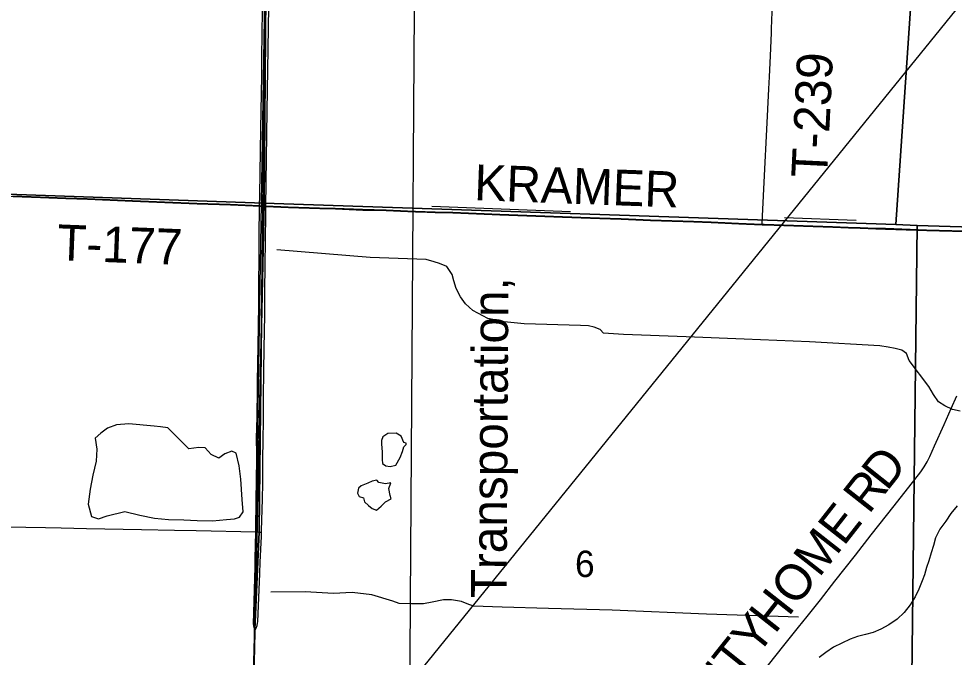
# Model space of a CAD drawing. Extents: x -107 to 120, y -81 to 213.
# Drawn here: x -76.39 to -68.55, y -24.78 to -19.43 of the extents above; entities that cross this region are included whole.
import ezdxf

# ---------------------------------------------------------------- set-up
doc = ezdxf.new("R2010")
doc.units = 0
for name, color, linetype in [('Default', 7, 'Continuous'), ('GM_X_Major_River', 7, 'Continuous'), ('GM_X_Minor_Lake', 7, 'Continuous'), ('GM_X_Minor_River', 7, 'Continuous'), ('GM_X_Rail_Line', 7, 'Continuous'), ('GM_X_Rail_Line_Text', 7, 'Continuous'), ('GM_X_Section', 7, 'Continuous'), ('GM_X_Section_Text', 7, 'Continuous'), ('GM_X_State_Route', 7, 'Continuous'), ('GM_X_Township', 7, 'Continuous'), ('GM_X_Township_Road', 7, 'Continuous'), ('GM_X_Township_Road_Text', 7, 'Continuous')]:
    doc.layers.add(name, color=color, linetype=linetype)

msp = doc.modelspace()

# ---------------------------------------------------------------- linework, layer by layer
at = {"layer": 'Default'}
msp.add_line((-74.4427, -26.637), (119.9981, 213.2739), dxfattribs=at)
at = {"layer": 'GM_X_Major_River'}
msp.add_lwpolyline([(-68.5289, -23.5056), (-68.5812, -23.5716), (-68.6254, -23.6357), (-68.6737, -23.7037), (-68.712, -23.7738), (-68.7262, -23.838), (-68.7464, -23.9001), (-68.7667, -23.9682), (-68.7849, -24.0223), (-68.8031, -24.0844), (-68.8213, -24.1345), (-68.8495, -24.2047), (-68.8818, -24.2687), (-68.9221, -24.3368), (-68.9723, -24.3989), (-69.0326, -24.4548), (-69.1009, -24.5028), (-69.1691, -24.5407), (-69.2333, -24.5666), (-69.2975, -24.5844), (-69.3636, -24.6023), (-69.4258, -24.6242), (-69.494, -24.6561), (-69.5662, -24.69), (-69.6305, -24.7339), (-69.6847, -24.7759)], dxfattribs=at)
at = {"layer": 'GM_X_Minor_Lake'}
for p, q in [((-75.2541, -22.84), (-75.4664, -22.8213)), ((-73.3514, -22.99), (-73.3456, -23.0542)), ((-73.4646, -23.3166), (-73.5208, -23.3405))]:
    msp.add_line(p, q, dxfattribs=at)
for points in [[(-75.4664, -22.8213), (-75.5706, -22.829), (-75.6449, -22.8569), (-75.7031, -22.8989), (-75.7493, -22.9408), (-75.7355, -23.0311), (-75.7419, -23.1334), (-75.7683, -23.2497), (-75.7907, -23.3679), (-75.8091, -23.4943), (-75.7793, -23.5966), (-75.7213, -23.6169), (-75.6491, -23.591), (-75.5007, -23.5553), (-75.3746, -23.5858), (-75.2525, -23.6102), (-75.1343, -23.6226), (-75.0061, -23.625), (-74.8939, -23.6293), (-74.7657, -23.6317), (-74.6495, -23.622), (-74.5814, -23.6162), (-74.5413, -23.6023), (-74.5111, -23.5583), (-74.5188, -23.4539), (-74.5303, -23.2834), (-74.544, -23.171), (-74.5677, -23.0647), (-74.6057, -23.0485), (-74.6619, -23.0724), (-74.714, -23.1084), (-74.7781, -23.0781), (-74.828, -23.0218), (-74.8801, -23.0176), (-74.9662, -23.0294), (-75.0242, -22.9711), (-75.098, -22.8946), (-75.14, -22.8544), (-75.2021, -22.8442), (-75.2541, -22.84)], [(-73.3456, -23.0542), (-73.3457, -23.0823), (-73.3458, -23.1184), (-73.3439, -23.1525), (-73.3159, -23.1726), (-73.2778, -23.1768), (-73.2317, -23.1669), (-73.1955, -23.1028), (-73.1753, -23.0527), (-73.1632, -23.0126), (-73.1451, -22.9926), (-73.145, -22.9826), (-73.165, -22.9765), (-73.1869, -22.9223), (-73.2289, -22.8981), (-73.299, -22.9019), (-73.3412, -22.9299), (-73.3513, -22.9599), (-73.3514, -22.99)], [(-73.5208, -23.3405), (-73.5448, -23.3585), (-73.553, -23.4006), (-73.537, -23.4287), (-73.503, -23.4409), (-73.4931, -23.473), (-73.4591, -23.5052), (-73.4292, -23.5293), (-73.3931, -23.5435), (-73.355, -23.5095), (-73.3188, -23.4735), (-73.2707, -23.4496), (-73.2786, -23.4195), (-73.2884, -23.3613), (-73.2723, -23.3152), (-73.3184, -23.3231), (-73.3744, -23.3129), (-73.3904, -23.2928), (-73.4285, -23.3007), (-73.4646, -23.3166)]]:
    msp.add_lwpolyline(points, dxfattribs=at)
at = {"layer": 'GM_X_Minor_River'}
for points in [[(-71.7668, -21.0449), (-72.9286, -20.9994)], [(-69.375, -21.1161), (-69.976, -21.0943)], [(-68.5044, -22.7153), (-68.5685, -22.7011), (-68.6325, -22.6688), (-68.6845, -22.6346), (-68.7284, -22.5743), (-68.7662, -22.508), (-68.9318, -22.2888), (-68.9537, -22.2306), (-68.9917, -22.2024), (-69.0497, -22.1882), (-69.1078, -22.178), (-69.1759, -22.1658), (-69.7668, -22.134), (-70.3136, -22.1123), (-70.8004, -22.0928), (-71.3252, -22.0732), (-71.4914, -22.0607), (-71.5194, -22.0306), (-71.5694, -22.0103), (-71.6175, -22.0002), (-71.6836, -21.998), (-72.1563, -21.9826), (-72.3241, -21.9654), (-72.4607, -21.9375), (-72.5867, -21.871), (-72.6466, -21.8146), (-72.6885, -21.7563), (-72.7244, -21.686), (-72.7462, -21.6238), (-72.7601, -21.5696), (-72.804, -21.5013), (-72.864, -21.477), (-72.91, -21.4628), (-72.9761, -21.4446), (-73.4468, -21.4272), (-74.2279, -21.3627)], [(-69.8579, -24.4384), (-70.6292, -24.4141), (-71.4184, -24.3797), (-71.9532, -24.3661), (-72.3399, -24.3549), (-72.5802, -24.3462), (-72.6323, -24.328), (-72.6823, -24.3078), (-72.7644, -24.2935), (-72.8325, -24.2953), (-72.9267, -24.3131), (-72.9989, -24.3269), (-73.101, -24.3266), (-73.2032, -24.3263), (-73.2572, -24.3041), (-73.4314, -24.2534), (-73.5956, -24.2329), (-73.7539, -24.2404), (-73.9902, -24.2277), (-74.2767, -24.2289)]]:
    msp.add_lwpolyline(points, dxfattribs=at)
at = {"layer": 'GM_X_Rail_Line'}
for points in [[(-73.2734, -42.3003), (-73.2649, -39.1049), (-73.2216, -37.066), (-73.1836, -32.1627), (-73.1217, -26.6694), (-73.1077, -24.2984), (-73.0594, -17.2912), (-73.0254, -15.4202), (-73.0009, -14.7079), (-72.9769, -14.4026), (-72.9056, -13.7921), (-72.6989, -11.6944), (-72.6592, -11.2717), (-72.6185, -10.8402), (-72.6072, -10.5527), (-72.6015, -10.2681), (-72.5873, -9.1338), (-72.5717, -7.0133)], [(-74.7234, -53.134), (-74.6362, -47.8623), (-74.5798, -37.2388), (-74.4951, -29.4853), (-74.4481, -26.6247), (-74.401, -23.7172), (-74.3109, -18.2221), (-74.335, -14.312), (-74.2191, -9.0155)]]:
    msp.add_lwpolyline(points, dxfattribs=at)
at = {"layer": 'GM_X_Section'}
for points in [[(-79.7136, -15.4834), (-74.2995, -15.6503), (-74.2925, -15.7245), (-74.3332, -20.9721), (-79.6709, -20.7861)], [(-74.2925, -15.7245), (-68.6864, -15.892), (-69.0434, -21.1516), (-74.3332, -20.9721)], [(-68.6864, -15.892), (-63.3999, -15.981), (-63.5863, -21.3171), (-68.8654, -21.1579), (-69.0434, -21.1516)], [(-79.6709, -20.7861), (-74.3332, -20.9721), (-74.4572, -26.6128), (-79.8137, -26.4946)], [(-74.3332, -20.9721), (-69.0434, -21.1516), (-68.8654, -21.1579), (-68.9331, -27.0735), (-74.4587, -26.8789), (-74.4572, -26.6128)], [(-68.8654, -21.1579), (-63.5863, -21.3171), (-63.5383, -21.3196), (-63.6604, -27.1446), (-68.9331, -27.0735)]]:
    msp.add_lwpolyline(points, close=True, dxfattribs=at)
at = {"layer": 'GM_X_State_Route'}
msp.add_line((-74.4046, -23.726), (-74.4002, -23.4428), dxfattribs=at)
for points in [[(-74.3725, -20.9978), (-74.3714, -20.9063), (-74.362, -20.3485), (-74.3545, -19.9055), (-74.3542, -19.7578), (-74.3534, -19.7087), (-74.3498, -19.5948), (-74.3468, -19.3159), (-74.3464, -19.2339), (-74.3403, -18.9551), (-74.3391, -18.8566), (-74.339, -18.8445)], [(-74.3189, -21.0001), (-74.3078, -20.1988), (-74.3036, -19.8543), (-74.296, -19.3292), (-74.2938, -19.1324), (-74.2919, -19.001), (-74.2894, -18.8863), (-74.2892, -18.8451)], [(-74.4002, -23.4428), (-74.3998, -23.4165), (-74.3994, -23.3345), (-74.3955, -23.072), (-74.3968, -22.9407), (-74.3927, -22.7604), (-74.3902, -22.5306), (-74.3889, -22.4651), (-74.3837, -22.1698), (-74.3798, -21.8252), (-74.3755, -21.2509), (-74.3725, -20.9978)], [(-74.3489, -23.4502), (-74.3462, -23.3161), (-74.3457, -23.1027), (-74.343, -22.9715), (-74.3401, -22.7747), (-74.3385, -22.6106), (-74.3355, -22.3645), (-74.3305, -22.0363), (-74.3282, -21.9216), (-74.3273, -21.7083), (-74.3198, -21.0684), (-74.3189, -21.0001)], [(-74.3575, -23.7646), (-74.3558, -23.7271), (-74.3553, -23.7139), (-74.3489, -23.4502)], [(-74.4084, -23.9804), (-74.4081, -23.9517), (-74.4046, -23.726)], [(-74.4098, -24.5459), (-74.4008, -24.532), (-74.3926, -24.5098), (-74.3894, -24.491), (-74.3878, -24.4771), (-74.3701, -24.0732), (-74.3671, -23.9787), (-74.3575, -23.7646)], [(-74.4098, -24.5459), (-74.418, -24.527), (-74.4213, -24.5123), (-74.4227, -24.4926), (-74.4193, -24.4018), (-74.4094, -24.0181), (-74.4084, -23.9804)], [(-74.4313, -25.7287), (-74.4303, -25.5642), (-74.4297, -25.5388), (-74.4285, -25.4823), (-74.4272, -25.3597), (-74.4264, -25.2802), (-74.4258, -25.2195), (-74.4244, -25.0885), (-74.4234, -25.0056), (-74.4223, -24.9089), (-74.4212, -24.8458), (-74.4201, -24.8081), (-74.4098, -24.5459)]]:
    msp.add_lwpolyline(points, dxfattribs=at)
at = {"layer": 'GM_X_Township'}
for points in [[(-74.3142, -18.8422), (-74.3456, -20.996), (-74.3737, -20.9948), (-74.618, -20.9846), (-74.8969, -20.9752), (-75.4379, -20.9519), (-75.8151, -20.9365), (-75.9954, -20.9291), (-76.2087, -20.9219), (-76.4383, -20.9136)], [(-68.3586, -21.2105), (-68.7852, -21.1985), (-69.1297, -21.1857), (-69.2117, -21.1831), (-69.3429, -21.1789), (-69.4412, -21.1749), (-69.5724, -21.1691), (-69.8185, -21.1608), (-70.1467, -21.1507), (-70.1648, -21.1499), (-70.3598, -21.1411), (-70.5896, -21.1323), (-70.7371, -21.1265), (-71.098, -21.114), (-71.344, -21.1029), (-71.5245, -21.0969), (-71.8362, -21.0868), (-71.9838, -21.081), (-72.3611, -21.0681), (-72.7548, -21.0515), (-72.9025, -21.047), (-73.0664, -21.0413), (-73.1319, -21.0388), (-73.3122, -21.0316), (-73.5091, -21.0266), (-73.7387, -21.0179), (-73.87, -21.013), (-74.1325, -21.0056), (-74.3201, -20.9972), (-74.3456, -20.996), (-74.3142, -18.8422)], [(-76.4383, -20.9136), (-76.2087, -20.9219), (-75.9954, -20.9291), (-75.8151, -20.9365), (-75.4379, -20.9519), (-74.8969, -20.9752), (-74.618, -20.9846), (-74.3737, -20.9948), (-74.3456, -20.996), (-74.3736, -23.4486), (-74.3768, -23.7238), (-74.411, -24.543), (-74.4213, -24.8052)], [(-74.4213, -24.8052), (-74.411, -24.543), (-74.3768, -23.7238), (-74.3736, -23.4486), (-74.3456, -20.996), (-74.3201, -20.9972), (-74.1325, -21.0056), (-73.87, -21.013), (-73.7387, -21.0179), (-73.5091, -21.0266), (-73.3122, -21.0316), (-73.1319, -21.0388), (-73.0664, -21.0413), (-72.9025, -21.047), (-72.7548, -21.0515), (-72.3611, -21.0681), (-71.9838, -21.081), (-71.8362, -21.0868), (-71.5245, -21.0969), (-71.344, -21.1029), (-71.098, -21.114), (-70.7371, -21.1265), (-70.5896, -21.1323), (-70.3598, -21.1411), (-70.1648, -21.1499), (-70.1467, -21.1507), (-69.8185, -21.1608), (-69.5724, -21.1691), (-69.4412, -21.1749), (-69.3429, -21.1789), (-69.2117, -21.1831), (-69.1297, -21.1857), (-68.7852, -21.1985), (-68.3586, -21.2105)]]:
    msp.add_lwpolyline(points, dxfattribs=at)
at = {"layer": 'GM_X_Township_Road'}
for p, q in [((-74.4256, -20.9955), (-74.3725, -20.9978)), ((-74.3725, -20.9978), (-74.3444, -20.999)), ((-74.3444, -20.999), (-74.3189, -21.0001)), ((-74.3756, -23.7267), (-74.3558, -23.7271))]:
    msp.add_line(p, q, dxfattribs=at)
for points in [[(-70.1636, -21.1528), (-70.1628, -21.136), (-70.1601, -21.0808), (-70.1433, -20.7395), (-70.1241, -20.3558), (-70.1069, -20.0148), (-70.1016, -19.9131), (-70.0937, -19.7392), (-70.0844, -19.5458), (-70.0834, -19.5198), (-70.0802, -19.4313), (-70.0739, -19.2804)], [(-79.6801, -20.8073), (-79.5515, -20.811), (-79.2235, -20.822), (-78.9118, -20.8308), (-78.6166, -20.8388), (-78.42, -20.8463), (-77.9935, -20.8612), (-77.6494, -20.8739), (-77.2394, -20.8892), (-77.0267, -20.8982), (-76.8308, -20.9039), (-76.4371, -20.9165), (-76.2075, -20.9248), (-75.9942, -20.9321), (-75.8139, -20.9394), (-75.4367, -20.9548), (-74.8957, -20.9781), (-74.6168, -20.9875), (-74.4256, -20.9955)], [(-74.3189, -21.0001), (-74.1313, -21.0085), (-73.8688, -21.016), (-73.7375, -21.0208), (-73.5079, -21.0295), (-73.311, -21.0345), (-73.1307, -21.0417), (-73.0652, -21.0442), (-73.0387, -21.0451)], [(-73.0387, -21.0451), (-72.9013, -21.0499), (-72.7536, -21.0544), (-72.3599, -21.071), (-71.9826, -21.0839), (-71.835, -21.0897), (-71.5233, -21.0999), (-71.3428, -21.1058), (-71.0968, -21.1169), (-70.7359, -21.1294), (-70.5884, -21.1352), (-70.3586, -21.144), (-70.1636, -21.1528)], [(-70.1636, -21.1528), (-70.1455, -21.1536), (-69.8173, -21.1637), (-69.5712, -21.1721), (-69.44, -21.1778), (-69.3417, -21.1818), (-69.2105, -21.186), (-69.1285, -21.1887), (-68.784, -21.2014), (-68.3574, -21.2135), (-68.3045, -21.2147)], [(-70.2256, -24.9854), (-69.9802, -24.6777), (-69.8583, -24.5233), (-69.7867, -24.4336), (-69.6738, -24.2929), (-69.5525, -24.138), (-69.3796, -23.9193), (-69.2489, -23.751), (-69.0562, -23.5061), (-68.8835, -23.2872), (-68.8344, -23.2216), (-68.8068, -23.1809), (-68.7816, -23.1387), (-68.7588, -23.0951), (-68.7177, -23.0057), (-68.6379, -22.8258), (-68.5781, -22.691), (-68.5321, -22.5858)], [(-77.0795, -23.6816), (-77.0478, -23.6775), (-77.0033, -23.6754), (-76.9212, -23.6765), (-76.593, -23.6829), (-76.3305, -23.6854), (-76.1664, -23.6889), (-76.0352, -23.6916), (-75.822, -23.6959), (-75.3625, -23.705), (-75.0836, -23.7107), (-74.9032, -23.7139), (-74.4046, -23.726)], [(-74.4046, -23.726), (-74.3823, -23.7265), (-74.3756, -23.7267)]]:
    msp.add_lwpolyline(points, dxfattribs=at)

# ---------------------------------------------------------------- texts
at = {"layer": 'GM_X_Rail_Line_Text'}
msp.add_text('Transportation,', height=0.299, rotation=89.66381, dxfattribs=at).set_placement((-72.3037, -24.282))
at = {"layer": 'GM_X_Section_Text'}
msp.add_text('6', height=0.221, rotation=0.00001, dxfattribs=at).set_placement((-71.7303, -24.1032))
at = {"layer": 'GM_X_Township_Road_Text'}
for s, rotation, p in [('T-239', 87.19615, (-69.6196, -20.7647)), ('KRAMER', 357.92007, (-72.5777, -20.9467)), ('T-177', 357.75434, (-76.0727, -21.4493)), ('D', 51.48696, (-69.117, -23.3906)), ('R', 51.84123, (-69.269, -23.584)), ('HOME', 51.89264, (-70.0569, -24.5875)), ('COUNTY', 51.41746, (-71.0991, -25.8891))]:
    msp.add_text(s, height=0.3, rotation=rotation, dxfattribs=at).set_placement(p)

doc.saveas('drawing.dxf')
